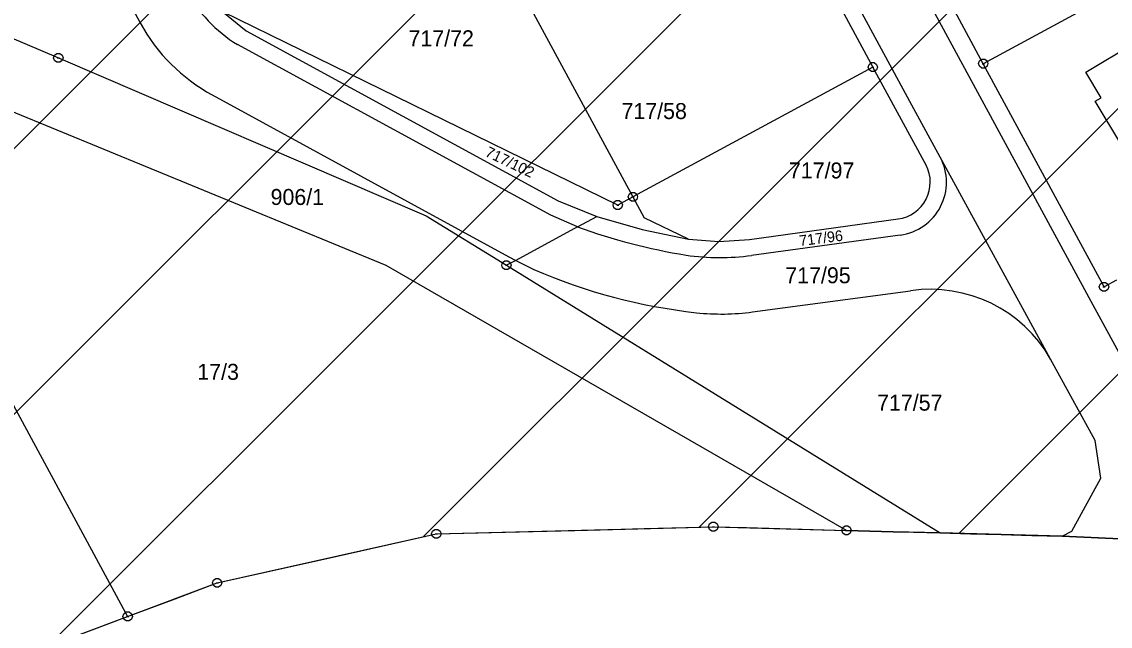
# Model space of a CAD drawing. Extents: x -593358 to -590116, y -1072518 to -1068420.
# Drawn here: x -591378.7 to -591263, y -1070372.5 to -1070308.2 of the extents above; entities that cross this region are included whole.
import ezdxf

# ---------------------------------------------------------------- set-up
doc = ezdxf.new("R2010")
doc.units = 0
for name, color, linetype in [('Parcela KN', 7, 'Continuous'), ('Parcelní číslo', 7, 'Continuous'), ('stavby - vnitřní kresba', 7, 'Continuous'), ('Vnitřní obvod', 7, 'Continuous'), ('Vrstva 24', 7, 'Continuous'), ('zastavitelné území', 7, 'Continuous')]:
    doc.layers.add(name, color=color, linetype=linetype)

msp = doc.modelspace()

# ---------------------------------------------------------------- linework, layer by layer
at = {"layer": 'Parcela KN'}
for p, q in [((-591284.08, -1070317.03), (-591316.22, -1070257.64)), ((-591379.3, -1070283.84), (-591366.13, -1070308.29)), ((-591302.97, -1070285.72), (-591288.22, -1070312.99)), ((-591276.48, -1070312.62), (-591289.33, -1070288.87)), ((-591328.48, -1070299.52), (-591313.73, -1070326.79)), ((-591250.98, -1070298.81), (-591276.48, -1070312.62)), ((-591315.34, -1070327.66), (-591357.34, -1070307.11)), ((-591357.34, -1070307.11), (-591354.86, -1070309.12)), ((-591265.57, -1070313.54), (-591258.21, -1070309.09)), ((-591380.05, -1070309.77), (-591374.82, -1070312.01)), ((-591354.86, -1070309.12), (-591321.7, -1070327.2)), ((-591399.97, -1070311.34), (-591367.46, -1070371.43)), ((-591322.46, -1070328.75), (-591355.77, -1070310.59)), ((-591374.82, -1070312.01), (-591335.72, -1070328.79)), ((-591288.22, -1070312.99), (-591313.73, -1070326.79)), ((-591282.56, -1070323.4), (-591288.22, -1070312.99)), ((-591263.63, -1070336.36), (-591276.48, -1070312.62)), ((-591263.95, -1070316.24), (-591265.57, -1070313.54)), ((-591358.47, -1070315.94), (-591326.93, -1070333.17)), ((-591281.05, -1070322.57), (-591284.08, -1070317.03)), ((-591264.57, -1070316.62), (-591263.95, -1070316.24)), ((-591261.73, -1070321.33), (-591264.57, -1070316.62)), ((-591339.96, -1070334.1), (-591379.95, -1070317.65)), ((-591269.32, -1070344.04), (-591281.05, -1070322.57)), ((-591321.7, -1070327.2), (-591317.58, -1070328.87)), ((-591313.73, -1070326.79), (-591315.34, -1070327.66)), ((-591313.73, -1070326.79), (-591312.53, -1070329.02)), ((-591335.72, -1070328.79), (-591327.18, -1070334.07)), ((-591319.64, -1070329.99), (-591322.46, -1070328.75)), ((-591319.64, -1070329.99), (-591317.58, -1070328.87)), ((-591317.58, -1070328.87), (-591312.75, -1070330.27)), ((-591307.82, -1070331.28), (-591312.53, -1070329.02)), ((-591301.35, -1070331.31), (-591285.54, -1070329.14)), ((-591319.64, -1070329.99), (-591326.2, -1070333.54)), ((-591312.75, -1070330.27), (-591307.82, -1070331.28)), ((-591285.31, -1070330.85), (-591301.12, -1070333.02)), ((-591307.82, -1070331.28), (-591304.59, -1070331.52)), ((-591304.59, -1070331.52), (-591301.35, -1070331.31)), ((-591326.93, -1070333.17), (-591326.2, -1070333.54)), ((-591291.02, -1070362.27), (-591339.96, -1070334.1)), ((-591326.2, -1070333.54), (-591327.18, -1070334.07)), ((-591327.18, -1070334.07), (-591281.07, -1070362.54)), ((-591326.2, -1070333.54), (-591324.27, -1070334.52)), ((-591262.32, -1070335.65), (-591263.63, -1070336.36)), ((-591301.02, -1070339.03), (-591284.21, -1070336.78)), ((-591264.58, -1070352.71), (-591269.32, -1070344.04)), ((-591263.98, -1070356.72), (-591264.58, -1070352.71)), ((-591267.07, -1070362.36), (-591263.98, -1070356.72)), ((-591334.64, -1070362.65), (-591305.18, -1070361.88)), ((-591305.18, -1070361.88), (-591291.02, -1070362.27)), ((-591291.02, -1070362.27), (-591281.07, -1070362.54)), ((-591357.94, -1070367.86), (-591334.64, -1070362.65)), ((-591281.07, -1070362.54), (-591268.08, -1070362.89)), ((-591268.08, -1070362.89), (-591267.07, -1070362.36)), ((-591268.08, -1070362.89), (-591249.63, -1070363.74)), ((-591367.46, -1070371.43), (-591357.94, -1070367.86)), ((-591378.03, -1070375.39), (-591367.46, -1070371.43))]:
    msp.add_line(p, q, dxfattribs=at)
for centre, radius, start, end in [((-591347.632, -1070297.363), 15.531, 208.65478, 238.39719), ((-591349.191, -1070298.989), 19.324, 208.77071, 241.30414), ((-591286.063, -1070325.227), 5.673, 277.62612, 27.9229), ((-591286.074, -1070325.219), 3.957, 277.75465, 27.37194), ((-591297.472, -1070268.305), 65.548, 250.23261, 260.69504), ((-591304.488, -1070308.176), 25.071, 261.78538, 277.71998), ((-591300.353, -1070279.287), 60.189, 246.58639, 263.67869), ((-591282.076, -1070351.303), 14.679, 29.65659, 98.35795), ((-591304.33, -1070314.47), 24.782, 263.86205, 277.676)]:
    msp.add_arc(centre, radius, start, end, dxfattribs=at)
at = {"layer": 'stavby - vnitřní kresba'}
for p, q in [((-591310.26, -1070254.42), (-591265.03, -1070337.88)), ((-591265.03, -1070337.88), (-591253.31, -1070359.54))]:
    msp.add_line(p, q, dxfattribs=at)
at = {"layer": 'Vnitřní obvod'}
msp.add_lwpolyline([(-591372.745, -1070373.41), (-591367.46, -1070371.43), (-591362.7, -1070369.645), (-591357.94, -1070367.86), (-591345.583, -1070365.097), (-591340.465, -1070363.953), (-591334.64, -1070362.65), (-591327.275, -1070362.458), (-591319.91, -1070362.265), (-591312.545, -1070362.073), (-591305.18, -1070361.88), (-591301.64, -1070361.978), (-591298.1, -1070362.075), (-591294.56, -1070362.173), (-591291.02, -1070362.27), (-591288.532, -1070362.337), (-591286.045, -1070362.405), (-591283.557, -1070362.472), (-591281.07, -1070362.54), (-591277.823, -1070362.627), (-591274.575, -1070362.715), (-591271.328, -1070362.802), (-591268.08, -1070362.89), (-591263.468, -1070363.103), (-591258.855, -1070363.315)], dxfattribs=at)
at = {"layer": 'Vrstva 24'}
for p, q in [((-591374.94, -1070312.01), (-591374.7, -1070312.01)), ((-591288.34, -1070312.99), (-591288.1, -1070312.99)), ((-591276.6, -1070312.62), (-591276.36, -1070312.62)), ((-591313.85, -1070326.79), (-591313.61, -1070326.79)), ((-591315.46, -1070327.66), (-591315.22, -1070327.66)), ((-591327.3, -1070334.07), (-591327.06, -1070334.07)), ((-591263.75, -1070336.36), (-591263.51, -1070336.36)), ((-591305.3, -1070361.88), (-591305.06, -1070361.88)), ((-591291.14, -1070362.27), (-591290.9, -1070362.27)), ((-591334.76, -1070362.65), (-591334.52, -1070362.65)), ((-591358.06, -1070367.86), (-591357.82, -1070367.86)), ((-591367.58, -1070371.43), (-591367.34, -1070371.43))]:
    msp.add_line(p, q, dxfattribs=at)
for points in [[(-591374.67, -1070311.53), (-591374.42, -1070311.71), (-591374.32, -1070312), (-591374.42, -1070312.29), (-591374.67, -1070312.47), (-591374.98, -1070312.47), (-591375.23, -1070312.29), (-591375.33, -1070312), (-591375.23, -1070311.71), (-591374.98, -1070311.53)], [(-591288.07, -1070312.51), (-591287.82, -1070312.69), (-591287.72, -1070312.98), (-591287.82, -1070313.27), (-591288.07, -1070313.45), (-591288.38, -1070313.45), (-591288.63, -1070313.27), (-591288.73, -1070312.98), (-591288.63, -1070312.69), (-591288.38, -1070312.51)], [(-591276.33, -1070312.14), (-591276.08, -1070312.32), (-591275.98, -1070312.61), (-591276.08, -1070312.9), (-591276.33, -1070313.08), (-591276.64, -1070313.08), (-591276.89, -1070312.9), (-591276.99, -1070312.61), (-591276.89, -1070312.32), (-591276.64, -1070312.14)], [(-591313.58, -1070326.31), (-591313.33, -1070326.49), (-591313.23, -1070326.78), (-591313.33, -1070327.07), (-591313.58, -1070327.25), (-591313.89, -1070327.25), (-591314.14, -1070327.07), (-591314.24, -1070326.78), (-591314.14, -1070326.49), (-591313.89, -1070326.31)], [(-591315.19, -1070327.18), (-591314.94, -1070327.36), (-591314.84, -1070327.65), (-591314.94, -1070327.94), (-591315.19, -1070328.12), (-591315.5, -1070328.12), (-591315.75, -1070327.94), (-591315.85, -1070327.65), (-591315.75, -1070327.36), (-591315.5, -1070327.18)], [(-591327.03, -1070333.59), (-591326.78, -1070333.77), (-591326.68, -1070334.06), (-591326.78, -1070334.35), (-591327.03, -1070334.53), (-591327.34, -1070334.53), (-591327.59, -1070334.35), (-591327.69, -1070334.06), (-591327.59, -1070333.77), (-591327.34, -1070333.59)], [(-591263.48, -1070335.88), (-591263.23, -1070336.06), (-591263.13, -1070336.35), (-591263.23, -1070336.64), (-591263.48, -1070336.82), (-591263.79, -1070336.82), (-591264.04, -1070336.64), (-591264.14, -1070336.35), (-591264.04, -1070336.06), (-591263.79, -1070335.88)], [(-591334.49, -1070362.17), (-591334.24, -1070362.35), (-591334.14, -1070362.64), (-591334.24, -1070362.93), (-591334.49, -1070363.11), (-591334.8, -1070363.11), (-591335.05, -1070362.93), (-591335.15, -1070362.64), (-591335.05, -1070362.35), (-591334.8, -1070362.17)], [(-591305.03, -1070361.4), (-591304.78, -1070361.58), (-591304.68, -1070361.87), (-591304.78, -1070362.16), (-591305.03, -1070362.34), (-591305.34, -1070362.34), (-591305.59, -1070362.16), (-591305.69, -1070361.87), (-591305.59, -1070361.58), (-591305.34, -1070361.4)], [(-591290.87, -1070361.79), (-591290.62, -1070361.97), (-591290.52, -1070362.26), (-591290.62, -1070362.55), (-591290.87, -1070362.73), (-591291.18, -1070362.73), (-591291.43, -1070362.55), (-591291.53, -1070362.26), (-591291.43, -1070361.97), (-591291.18, -1070361.79)], [(-591357.79, -1070367.38), (-591357.54, -1070367.56), (-591357.44, -1070367.85), (-591357.54, -1070368.14), (-591357.79, -1070368.32), (-591358.1, -1070368.32), (-591358.35, -1070368.14), (-591358.45, -1070367.85), (-591358.35, -1070367.56), (-591358.1, -1070367.38)], [(-591367.31, -1070370.95), (-591367.06, -1070371.13), (-591366.96, -1070371.42), (-591367.06, -1070371.71), (-591367.31, -1070371.89), (-591367.62, -1070371.89), (-591367.87, -1070371.71), (-591367.97, -1070371.42), (-591367.87, -1070371.13), (-591367.62, -1070370.95)]]:
    msp.add_lwpolyline(points, close=True, dxfattribs=at)
at = {"layer": 'zastavitelné území'}
for p, q in [((-591513.288, -1070455.368), (-591170.017, -1070112.097)), ((-591467.818, -1070438.181), (-591160.472, -1070130.836)), ((-591375.97, -1070374.618), (-591146.829, -1070145.477)), ((-591336.028, -1070362.96), (-591136.942, -1070163.875)), ((-591306.703, -1070361.92), (-591132.384, -1070187.601)), ((-591279.092, -1070362.593), (-591121.21, -1070204.711))]:
    msp.add_line(p, q, dxfattribs=at)
for points in [[(-591372.745, -1070373.41), (-591367.46, -1070371.43), (-591362.7, -1070369.645), (-591357.94, -1070367.86), (-591346.29, -1070365.255), (-591334.64, -1070362.65), (-591319.91, -1070362.265), (-591305.18, -1070361.88), (-591298.1, -1070362.075), (-591291.02, -1070362.27)], [(-591118.19, -1070371.58), (-591160.73, -1070368.88), (-591203.27, -1070366.18), (-591226.085, -1070364.98), (-591248.9, -1070363.78), (-591258.855, -1070363.315), (-591268.08, -1070362.89), (-591274.575, -1070362.715), (-591281.07, -1070362.54), (-591286.045, -1070362.405), (-591291.02, -1070362.27)]]:
    msp.add_lwpolyline(points, dxfattribs=at)

# ---------------------------------------------------------------- texts
at = {"layer": 'Parcelní číslo'}
for s, p in [('717/72', (-591337.598, -1070310.77)), ('717/58', (-591314.951, -1070318.51)), ('717/97', (-591297.144, -1070324.83)), ('906/1', (-591352.262, -1070327.65)), ('717/95', (-591297.531, -1070335.98)), ('17/3', (-591360.053, -1070346.25)), ('717/57', (-591287.771, -1070349.53))]:
    msp.add_text(s, height=1.7, dxfattribs=at).set_placement(p)
for s, rotation, p in [('717/102', 334.32087, (-591329.539, -1070322.408)), ('717/96', 7.33386, (-591295.967, -1070332.036))]:
    msp.add_text(s, height=1.14, rotation=rotation, dxfattribs=at).set_placement(p)

doc.saveas('drawing.dxf')
